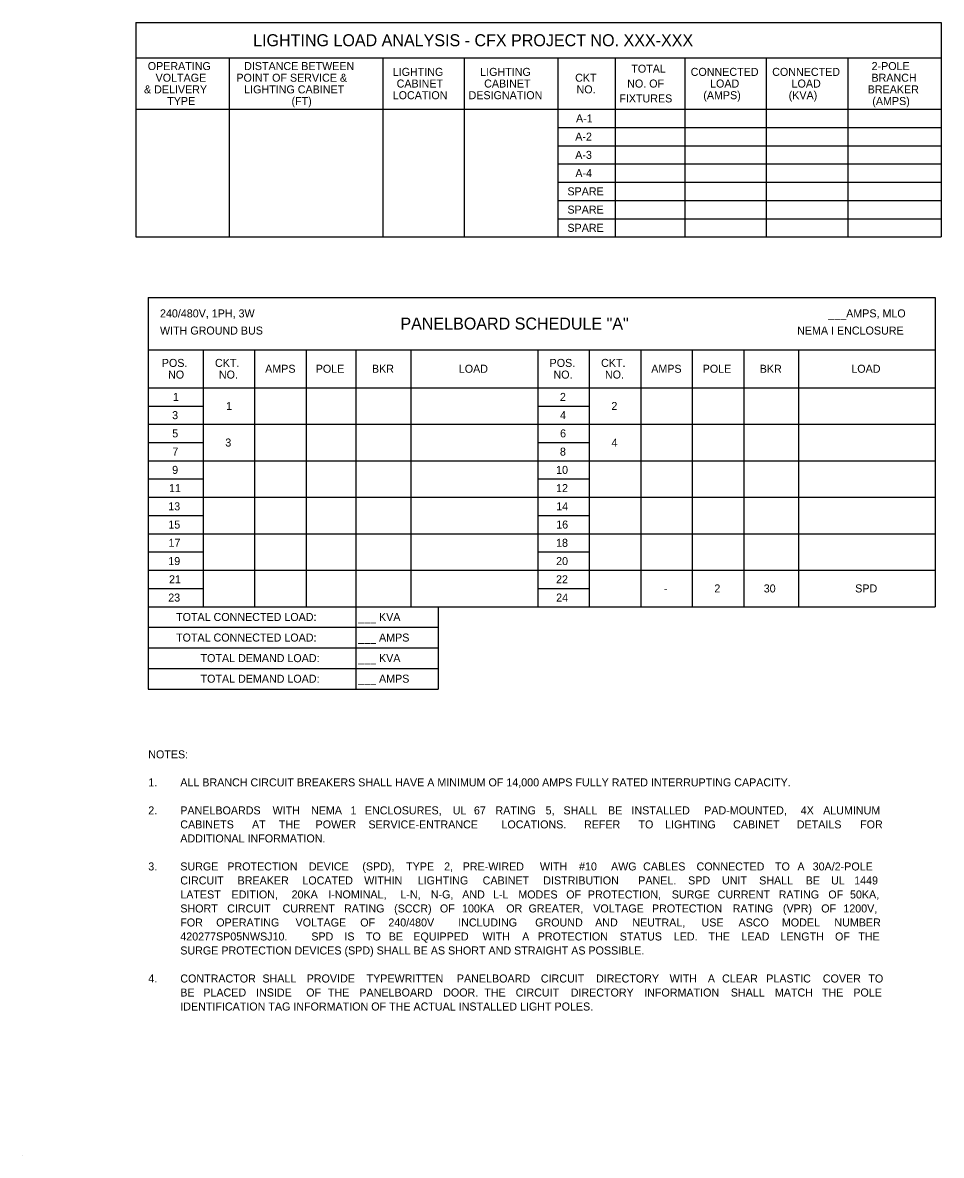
# Model space of a CAD drawing. Extents: x 856079 to 2148480, y 462635 to 2147771.
# Drawn here: x 2148464.67 to 2148472.7, y 2147761.57 to 2147771.47 of the extents above; entities that cross this region are included whole.
import ezdxf

# ---------------------------------------------------------------- set-up
doc = ezdxf.new("R2010")
doc.units = 0
for name, color, linetype in [('AdhocPoint_dp', 7, 'Continuous'), ('FLMap5', 7, 'Continuous'), ('SumBoxBorder_dp', 7, 'Continuous'), ('SumBoxLines_dp', 7, 'Continuous'), ('TextNotes', 7, 'Continuous')]:
    doc.layers.add(name, color=color, linetype=linetype)

msp = doc.modelspace()

# ---------------------------------------------------------------- linework, layer by layer
at = {"layer": 'AdhocPoint_dp'}
msp.add_line((2148464.6682, 2147761.5674), (2148464.6682, 2147761.5674), dxfattribs=at)
at = {"layer": 'SumBoxBorder_dp'}
for p, q in [((2148465.6565, 2147771.4724), (2148472.699, 2147771.4724)), ((2148465.6565, 2147771.4724), (2148465.6565, 2147769.5984)), ((2148472.699, 2147771.4724), (2148472.699, 2147769.5984)), ((2148465.6565, 2147771.1649), (2148472.699, 2147771.1649)), ((2148465.6565, 2147771.1649), (2148472.699, 2147771.1649)), ((2148465.6565, 2147769.5984), (2148472.699, 2147769.5984)), ((2148465.7662, 2147769.0699), (2148472.6437, 2147769.0699)), ((2148465.7662, 2147769.0699), (2148465.7662, 2147765.6454)), ((2148472.6437, 2147769.0699), (2148472.6437, 2147766.3654)), ((2148465.7662, 2147768.6124), (2148472.6437, 2147768.6124)), ((2148465.7662, 2147768.6124), (2148472.6437, 2147768.6124)), ((2148465.7662, 2147766.3654), (2148472.6437, 2147766.3654)), ((2148465.7662, 2147766.3654), (2148472.6437, 2147766.3654)), ((2148467.5812, 2147766.3654), (2148467.5812, 2147765.6454)), ((2148468.3012, 2147766.3654), (2148468.3012, 2147765.6454)), ((2148468.3012, 2147766.3654), (2148468.3012, 2147765.6454)), ((2148465.7662, 2147766.1854), (2148468.3012, 2147766.1854)), ((2148465.7662, 2147766.1854), (2148468.3012, 2147766.1854)), ((2148465.7662, 2147766.0054), (2148468.3012, 2147766.0054)), ((2148465.7662, 2147766.0054), (2148468.3012, 2147766.0054)), ((2148465.7662, 2147765.8254), (2148468.3012, 2147765.8254)), ((2148465.7662, 2147765.8254), (2148468.3012, 2147765.8254)), ((2148465.7662, 2147765.6454), (2148468.3012, 2147765.6454))]:
    msp.add_line(p, q, dxfattribs=at)
at = {"layer": 'SumBoxLines_dp'}
for p, q in [((2148466.474, 2147771.1649), (2148466.474, 2147769.5984)), ((2148466.474, 2147771.1649), (2148466.474, 2147769.5984)), ((2148467.8165, 2147771.1649), (2148467.8165, 2147769.5984)), ((2148467.8165, 2147771.1649), (2148467.8165, 2147769.5984)), ((2148468.529, 2147771.1649), (2148468.529, 2147769.5984)), ((2148468.529, 2147771.1649), (2148468.529, 2147769.5984)), ((2148469.3465, 2147771.1649), (2148469.3465, 2147769.5984)), ((2148469.3465, 2147771.1649), (2148469.3465, 2147769.5984)), ((2148469.849, 2147771.1649), (2148469.849, 2147769.5984)), ((2148469.849, 2147771.1649), (2148469.849, 2147769.5984)), ((2148470.4565, 2147771.1649), (2148470.4565, 2147769.5984)), ((2148470.4565, 2147771.1649), (2148470.4565, 2147769.5984)), ((2148471.169, 2147771.1649), (2148471.169, 2147769.5984)), ((2148471.169, 2147771.1649), (2148471.169, 2147769.5984)), ((2148471.8815, 2147771.1649), (2148471.8815, 2147769.5984)), ((2148471.8815, 2147771.1649), (2148471.8815, 2147769.5984)), ((2148465.6565, 2147770.7149), (2148472.699, 2147770.7149)), ((2148465.6565, 2147770.7149), (2148472.699, 2147770.7149)), ((2148469.3465, 2147770.5554), (2148472.699, 2147770.5554)), ((2148469.3465, 2147770.5554), (2148472.699, 2147770.5554)), ((2148469.3465, 2147770.3959), (2148472.699, 2147770.3959)), ((2148469.3465, 2147770.3959), (2148472.699, 2147770.3959)), ((2148469.3465, 2147770.2364), (2148472.699, 2147770.2364)), ((2148469.3465, 2147770.2364), (2148472.699, 2147770.2364)), ((2148469.3465, 2147770.0769), (2148472.699, 2147770.0769)), ((2148469.3465, 2147770.0769), (2148472.699, 2147770.0769)), ((2148469.3465, 2147769.9174), (2148472.699, 2147769.9174)), ((2148469.3465, 2147769.9174), (2148472.699, 2147769.9174)), ((2148469.3465, 2147769.7579), (2148472.699, 2147769.7579)), ((2148469.3465, 2147769.7579), (2148472.699, 2147769.7579)), ((2148466.2462, 2147768.6124), (2148466.2462, 2147766.3654)), ((2148466.2462, 2147768.6124), (2148466.2462, 2147766.3654)), ((2148466.6962, 2147768.6124), (2148466.6962, 2147766.3654)), ((2148466.6962, 2147768.6124), (2148466.6962, 2147766.3654)), ((2148467.1462, 2147768.6124), (2148467.1462, 2147766.3654)), ((2148467.1462, 2147768.6124), (2148467.1462, 2147766.3654)), ((2148467.5812, 2147768.6124), (2148467.5812, 2147766.3654)), ((2148467.5812, 2147768.6124), (2148467.5812, 2147766.3654)), ((2148468.0612, 2147768.6124), (2148468.0612, 2147766.3654)), ((2148468.0612, 2147768.6124), (2148468.0612, 2147766.3654)), ((2148469.1712, 2147768.6124), (2148469.1712, 2147766.3654)), ((2148469.1712, 2147768.6124), (2148469.1712, 2147766.3654)), ((2148469.6212, 2147768.6124), (2148469.6212, 2147766.3654)), ((2148469.6212, 2147768.6124), (2148469.6212, 2147766.3654)), ((2148470.0712, 2147768.6124), (2148470.0712, 2147766.3654)), ((2148470.0712, 2147768.6124), (2148470.0712, 2147766.3654)), ((2148470.5212, 2147768.6124), (2148470.5212, 2147766.3654)), ((2148470.5212, 2147768.6124), (2148470.5212, 2147766.3654)), ((2148470.9712, 2147768.6124), (2148470.9712, 2147766.3654)), ((2148470.9712, 2147768.6124), (2148470.9712, 2147766.3654)), ((2148471.4512, 2147768.6124), (2148471.4512, 2147766.3654)), ((2148471.4512, 2147768.6124), (2148471.4512, 2147766.3654)), ((2148465.7662, 2147768.2794), (2148472.6437, 2147768.2794)), ((2148465.7662, 2147768.2794), (2148472.6437, 2147768.2794)), ((2148465.7662, 2147768.1199), (2148466.2462, 2147768.1199)), ((2148465.7662, 2147768.1199), (2148466.2462, 2147768.1199)), ((2148469.1712, 2147768.1199), (2148469.6212, 2147768.1199)), ((2148465.7662, 2147767.9604), (2148472.6437, 2147767.9604)), ((2148465.7662, 2147767.9604), (2148472.6437, 2147767.9604)), ((2148465.7662, 2147767.8009), (2148466.2462, 2147767.8009)), ((2148465.7662, 2147767.8009), (2148466.2462, 2147767.8009)), ((2148469.1712, 2147767.8009), (2148469.6212, 2147767.8009)), ((2148469.1712, 2147767.8009), (2148469.6212, 2147767.8009)), ((2148465.7662, 2147767.6414), (2148469.1712, 2147767.6414)), ((2148465.7662, 2147767.6414), (2148472.6437, 2147767.6414)), ((2148469.6212, 2147767.6414), (2148472.6437, 2147767.6414)), ((2148465.7662, 2147767.4819), (2148466.2462, 2147767.4819)), ((2148465.7662, 2147767.4819), (2148466.2462, 2147767.4819)), ((2148469.1712, 2147767.4819), (2148469.6212, 2147767.4819)), ((2148469.1712, 2147767.4819), (2148469.6212, 2147767.4819)), ((2148465.7662, 2147767.3224), (2148472.6437, 2147767.3224)), ((2148465.7662, 2147767.3224), (2148472.6437, 2147767.3224)), ((2148465.7662, 2147767.1629), (2148466.2462, 2147767.1629)), ((2148465.7662, 2147767.1629), (2148466.2462, 2147767.1629)), ((2148469.1712, 2147767.1629), (2148469.6212, 2147767.1629)), ((2148465.7662, 2147767.0034), (2148472.6437, 2147767.0034)), ((2148465.7662, 2147767.0034), (2148472.6437, 2147767.0034)), ((2148465.7662, 2147766.8439), (2148466.2462, 2147766.8439)), ((2148465.7662, 2147766.8439), (2148466.2462, 2147766.8439)), ((2148469.1712, 2147766.8439), (2148469.6212, 2147766.8439)), ((2148469.1712, 2147766.8439), (2148469.6212, 2147766.8439)), ((2148465.7662, 2147766.6844), (2148469.1712, 2147766.6844)), ((2148465.7662, 2147766.6844), (2148472.6437, 2147766.6844)), ((2148469.6212, 2147766.6844), (2148472.6437, 2147766.6844)), ((2148465.7662, 2147766.5249), (2148466.2462, 2147766.5249)), ((2148465.7662, 2147766.5249), (2148466.2462, 2147766.5249)), ((2148469.1712, 2147766.5249), (2148469.6212, 2147766.5249)), ((2148469.1712, 2147766.5249), (2148469.6212, 2147766.5249))]:
    msp.add_line(p, q, dxfattribs=at)

# ---------------------------------------------------------------- texts
at = {"layer": 'FLMap5'}
for s, height, p in [('LIGHTING LOAD ANALYSIS - CFX PROJECT NO. XXX-XXX', 0.105, (2148466.6829, 2147771.2662)), ('OPERATING', 0.07, (2148465.7617, 2147771.0579)), ('DISTANCE BETWEEN', 0.07, (2148466.6045, 2147771.0579)), ('TOTAL', 0.07, (2148469.9891, 2147771.0349)), ('2-POLE', 0.07, (2148472.0893, 2147771.0579)), ('VOLTAGE', 0.07, (2148465.8304, 2147770.9559)), ('POINT OF SERVICE &', 0.07, (2148466.5368, 2147770.9559)), ('LIGHTING', 0.07, (2148467.9031, 2147771.0069)), ('LIGHTING', 0.07, (2148468.6681, 2147771.0069)), ('CKT', 0.07, (2148469.4979, 2147770.9559)), ('CONNECTED', 0.07, (2148470.5081, 2147771.0069)), ('CONNECTED', 0.07, (2148471.2206, 2147771.0069)), ('BRANCH', 0.07, (2148472.0883, 2147770.9559)), ('& DELIVERY', 0.07, (2148465.7289, 2147770.8539)), ('LIGHTING CABINET', 0.07, (2148466.605, 2147770.8539)), ('CABINET', 0.07, (2148467.9374, 2147770.9049)), ('CABINET', 0.07, (2148468.7024, 2147770.9049)), ('NO.', 0.07, (2148469.5101, 2147770.8539)), ('NO. OF', 0.07, (2148469.9528, 2147770.9049)), ('LOAD', 0.07, (2148470.6775, 2147770.9049)), ('LOAD', 0.07, (2148471.39, 2147770.9049)), ('BREAKER', 0.07, (2148472.0553, 2147770.8539)), ('TYPE', 0.07, (2148465.932, 2147770.7519)), ('(FT)', 0.07, (2148467.0184, 2147770.7519)), ('LOCATION', 0.07, (2148467.9031, 2147770.8029)), ('DESIGNATION', 0.07, (2148468.5664, 2147770.8029)), ('FIXTURES', 0.07, (2148469.8842, 2147770.7749)), ('(AMPS)', 0.07, (2148470.6182, 2147770.8029)), ('(KVA)', 0.07, (2148471.3646, 2147770.8029)), ('(AMPS)', 0.07, (2148472.0957, 2147770.7519)), ('A-1', 0.07, (2148469.5054, 2147770.6002)), ('A-2', 0.07, (2148469.4986, 2147770.4407)), ('A-3', 0.07, (2148469.4986, 2147770.2812)), ('A-4', 0.07, (2148469.5, 2147770.1217)), ('SPARE', 0.07, (2148469.4306, 2147769.9622)), ('SPARE', 0.07, (2148469.4306, 2147769.8027)), ('SPARE', 0.07, (2148469.4306, 2147769.6432)), ('240/480V, 1PH, 3W', 0.07, (2148465.8687, 2147768.8949)), ('___AMPS, MLO', 0.07, (2148471.7109, 2147768.8949)), ('WITH GROUND BUS', 0.07, (2148465.8687, 2147768.7449)), ('PANELBOARD SCHEDULE "A"', 0.105, (2148467.9705, 2147768.7887)), ('NEMA I ENCLOSURE', 0.07, (2148471.4385, 2147768.7449)), ('POS.', 0.07, (2148465.8847, 2147768.4619)), ('CKT.', 0.07, (2148466.3497, 2147768.4619)), ('POS.', 0.07, (2148469.2747, 2147768.4619)), ('CKT.', 0.07, (2148469.7247, 2147768.4619)), ('NO', 0.07, (2148465.9394, 2147768.3599)), ('NO.', 0.07, (2148466.3835, 2147768.3599)), ('AMPS', 0.07, (2148466.7881, 2147768.4109)), ('POLE', 0.07, (2148467.2304, 2147768.4109)), ('BKR', 0.07, (2148467.7217, 2147768.4109)), ('LOAD', 0.07, (2148468.481, 2147768.4109)), ('NO.', 0.07, (2148469.3085, 2147768.3599)), ('NO.', 0.07, (2148469.7585, 2147768.3599)), ('AMPS', 0.07, (2148470.1631, 2147768.4109)), ('POLE', 0.07, (2148470.6129, 2147768.4109)), ('BKR', 0.07, (2148471.1117, 2147768.4109)), ('LOAD', 0.07, (2148471.9122, 2147768.4109)), ('1', 0.07, (2148465.9815, 2147768.1647)), ('2', 0.07, (2148469.3648, 2147768.1647)), ('1', 0.07, (2148466.4465, 2147768.0849)), ('2', 0.07, (2148469.8148, 2147768.0849)), ('3', 0.07, (2148465.9748, 2147768.0052)), ('4', 0.07, (2148469.3662, 2147768.0052)), ('5', 0.07, (2148465.9757, 2147767.8457)), ('6', 0.07, (2148469.3662, 2147767.8457)), ('3', 0.07, (2148466.4398, 2147767.7659)), ('4', 0.07, (2148469.8162, 2147767.7659)), ('7', 0.07, (2148465.9768, 2147767.6862)), ('8', 0.07, (2148469.365, 2147767.6862)), ('9', 0.07, (2148465.9752, 2147767.5267)), ('10', 0.07, (2148469.3315, 2147767.5267)), ('11', 0.07, (2148465.9477, 2147767.3672)), ('12', 0.07, (2148469.3309, 2147767.3672)), ('13', 0.07, (2148465.9409, 2147767.2077)), ('14', 0.07, (2148469.3323, 2147767.2077)), ('16', 0.07, (2148469.3323, 2147767.0482)), ('15', 0.07, (2148465.9418, 2147767.0482)), ('17', 0.07, (2148465.9429, 2147766.8887)), ('18', 0.07, (2148469.3312, 2147766.8887)), ('19', 0.07, (2148465.9413, 2147766.7292)), ('20', 0.07, (2148469.3315, 2147766.7292)), ('21', 0.07, (2148465.9477, 2147766.5697)), ('22', 0.07, (2148469.3309, 2147766.5697)), ('2', 0.07, (2148470.7148, 2147766.4899)), ('30', 0.07, (2148471.1465, 2147766.4899)), ('SPD', 0.07, (2148471.9461, 2147766.4899)), ('23', 0.07, (2148465.9409, 2147766.4102)), ('24', 0.07, (2148469.3323, 2147766.4102)), ('-', 0.07, (2148470.2727, 2147766.4899)), ('TOTAL CONNECTED LOAD:', 0.07, (2148466.0093, 2147766.2404)), ('___ KVA', 0.07, (2148467.6012, 2147766.2404)), ('TOTAL CONNECTED LOAD:', 0.07, (2148466.0093, 2147766.0604)), ('___ AMPS', 0.07, (2148467.6012, 2147766.0604)), ('TOTAL DEMAND LOAD:', 0.07, (2148466.2233, 2147765.8804)), ('___ KVA', 0.07, (2148467.6012, 2147765.8804)), ('TOTAL DEMAND LOAD:', 0.07, (2148466.2233, 2147765.7004)), ('___ AMPS', 0.07, (2148467.6012, 2147765.7004))]:
    msp.add_text(s, height=height, dxfattribs=at).set_placement(p)
at = {"layer": 'TextNotes'}
for s, p in [('NOTES:', (2148465.7662, 2147765.0389)), ('1.', (2148465.7662, 2147764.7939)), ('ALL BRANCH CIRCUIT BREAKERS SHALL HAVE A MINIMUM OF 14,000 AMPS FULLY RATED INTERRUPTING CAPACITY.', (2148466.0462, 2147764.7939)), ('2.', (2148465.7662, 2147764.5489)), ('PANELBOARDS ', (2148466.0462, 2147764.5489)), ('WITH ', (2148466.8531, 2147764.5489)), ('NEMA ', (2148467.1892, 2147764.5489)), ('1 ', (2148467.5342, 2147764.5489)), ('ENCLOSURES, ', (2148467.6599, 2147764.5489)), ('UL ', (2148468.4276, 2147764.5489)), ('67 ', (2148468.613, 2147764.5489)), ('RATING ', (2148468.8015, 2147764.5489)), ('5, ', (2148469.2397, 2147764.5489)), ('SHALL ', (2148469.396, 2147764.5489)), ('BE ', (2148469.7854, 2147764.5489)), ('INSTALLED ', (2148469.9904, 2147764.5489)), ('PAD-MOUNTED, ', (2148470.6258, 2147764.5489)), ('4X ', (2148471.4699, 2147764.5489)), ('ALUMINUM ', (2148471.6658, 2147764.5489)), ('CABINETS ', (2148466.0462, 2147764.4264)), ('AT ', (2148466.6733, 2147764.4264)), ('THE ', (2148466.9072, 2147764.4264)), ('POWER ', (2148467.229, 2147764.4264)), ('SERVICE-ENTRANCE ', (2148467.691, 2147764.4264)), ('LOCATIONS. ', (2148468.8538, 2147764.4264)), (' REFER ', (2148469.5492, 2147764.4264)), ('TO ', (2148470.0517, 2147764.4264)), ('LIGHTING ', (2148470.2851, 2147764.4264)), ('CABINET ', (2148470.8792, 2147764.4264)), ('DETAILS ', (2148471.4355, 2147764.4264)), ('FOR ', (2148471.9891, 2147764.4264)), ('ADDITIONAL INFORMATION.', (2148466.0462, 2147764.3039)), ('3.', (2148465.7662, 2147764.0589)), ('SURGE ', (2148466.0462, 2147764.0589)), ('PROTECTION ', (2148466.4572, 2147764.0589)), ('DEVICE ', (2148467.17, 2147764.0589)), ('(SPD), ', (2148467.6377, 2147764.0589)), ('TYPE ', (2148468.0205, 2147764.0589)), ('2, ', (2148468.3525, 2147764.0589)), ('PRE-WIRED ', (2148468.5148, 2147764.0589)), ('WITH ', (2148469.1899, 2147764.0589)), ('#10 ', (2148469.5321, 2147764.0589)), ('AWG ', (2148469.8114, 2147764.0589)), ('CABLES ', (2148470.0921, 2147764.0589)), ('CONNECTED ', (2148470.5591, 2147764.0589)), ('TO ', (2148471.245, 2147764.0589)), ('A ', (2148471.4413, 2147764.0589)), ('30A/2-POLE ', (2148471.5744, 2147764.0589)), ('CIRCUIT ', (2148466.0462, 2147763.9364)), ('BREAKER ', (2148466.5472, 2147763.9364)), ('LOCATED ', (2148467.1135, 2147763.9364)), ('WITHIN ', (2148467.654, 2147763.9364)), ('LIGHTING ', (2148468.1216, 2147763.9364)), ('CABINET ', (2148468.6893, 2147763.9364)), ('DISTRIBUTION ', (2148469.2193, 2147763.9364)), ('PANEL. ', (2148470.0496, 2147763.9364)), ('SPD ', (2148470.4858, 2147763.9364)), ('UNIT ', (2148470.7817, 2147763.9364)), ('SHALL ', (2148471.1069, 2147763.9364)), ('BE ', (2148471.5131, 2147763.9364)), ('UL ', (2148471.7348, 2147763.9364)), ('1449 ', (2148471.937, 2147763.9364)), ('LATEST ', (2148466.0462, 2147763.8139)), ('EDITION, ', (2148466.4942, 2147763.8139)), ('20KA ', (2148467.0192, 2147763.8139)), ('I-NOMINAL, ', (2148467.3393, 2147763.8139)), ('L-N, ', (2148467.9703, 2147763.8139)), ('N-G, ', (2148468.2361, 2147763.8139)), ('AND ', (2148468.5106, 2147763.8139)), ('L-L ', (2148468.7797, 2147763.8139)), ('MODES ', (2148469.0011, 2147763.8139)), ('OF ', (2148469.4198, 2147763.8139)), ('PROTECTION, ', (2148469.6094, 2147763.8139)), ('SURGE ', (2148470.3427, 2147763.8139)), ('CURRENT ', (2148470.7435, 2147763.8139)), ('RATING ', (2148471.2769, 2147763.8139)), ('OF ', (2148471.7111, 2147763.8139)), ('50KA, ', (2148471.9007, 2147763.8139)), ('SHORT ', (2148466.0462, 2147763.6914)), ('CIRCUIT ', (2148466.4564, 2147763.6914)), ('CURRENT ', (2148466.9403, 2147763.6914)), ('RATING ', (2148467.4775, 2147763.6914)), ('(SCCR) ', (2148467.9154, 2147763.6914)), ('OF ', (2148468.3157, 2147763.6914)), ('100KA ', (2148468.5091, 2147763.6914)), ('OR ', (2148468.8958, 2147763.6914)), ('GREATER, ', (2148469.0907, 2147763.6914)), ('VOLTAGE ', (2148469.656, 2147763.6914)), ('PROTECTION ', (2148470.1694, 2147763.6914)), ('RATING ', (2148470.8758, 2147763.6914)), ('(VPR) ', (2148471.3137, 2147763.6914)), ('OF ', (2148471.649, 2147763.6914)), ('1200V, ', (2148471.8424, 2147763.6914)), ('FOR ', (2148466.0462, 2147763.5689)), ('OPERATING ', (2148466.3603, 2147763.5689)), ('VOLTAGE ', (2148467.0539, 2147763.5689)), ('OF ', (2148467.6192, 2147763.5689)), ('240/480V ', (2148467.8646, 2147763.5689)), ('INCLUDING ', (2148468.4754, 2147763.5689)), ('GROUND ', (2148469.1484, 2147763.5689)), ('AND ', (2148469.6727, 2147763.5689)), ('NEUTRAL, ', (2148469.9976, 2147763.5689)), ('USE ', (2148470.6026, 2147763.5689)), ('ASCO ', (2148470.9263, 2147763.5689)), ('MODEL ', (2148471.305, 2147763.5689)), ('NUMBER ', (2148471.7642, 2147763.5689)), ('420277SP05NWSJ10. ', (2148466.0462, 2147763.4464)), ('SPD ', (2148467.1915, 2147763.4464)), ('IS ', (2148467.4803, 2147763.4464)), ('TO ', (2148467.6688, 2147763.4464)), ('BE ', (2148467.8687, 2147763.4464)), ('EQUIPPED ', (2148468.0833, 2147763.4464)), ('WITH ', (2148468.6887, 2147763.4464)), ('A ', (2148469.0345, 2147763.4464)), ('PROTECTION ', (2148469.1711, 2147763.4464)), ('STATUS ', (2148469.8875, 2147763.4464)), ('LED. ', (2148470.3602, 2147763.4464)), ('THE ', (2148470.6639, 2147763.4464)), ('LEAD ', (2148470.9522, 2147763.4464)), ('LENGTH ', (2148471.2925, 2147763.4464)), ('OF ', (2148471.7697, 2147763.4464)), ('THE ', (2148471.973, 2147763.4464)), ('SURGE PROTECTION DEVICES (SPD) SHALL BE AS SHORT AND STRAIGHT AS POSSIBLE.', (2148466.0462, 2147763.3239)), ('4.', (2148465.7662, 2147763.0789)), ('CONTRACTOR ', (2148466.0462, 2147763.0789)), ('SHALL ', (2148466.764, 2147763.0789)), ('PROVIDE ', (2148467.1512, 2147763.0789)), ('TYPEWRITTEN ', (2148467.6747, 2147763.0789)), ('PANELBOARD ', (2148468.4642, 2147763.0789)), ('CIRCUIT ', (2148469.1981, 2147763.0789)), ('DIRECTORY ', (2148469.6801, 2147763.0789)), ('WITH ', (2148470.3241, 2147763.0789)), ('A ', (2148470.658, 2147763.0789)), ('CLEAR ', (2148470.7827, 2147763.0789)), ('PLASTIC ', (2148471.1687, 2147763.0789)), ('COVER ', (2148471.663, 2147763.0789)), ('TO ', (2148472.0613, 2147763.0789)), ('BE ', (2148466.0462, 2147762.9564)), ('PLACED ', (2148466.2474, 2147762.9564)), ('INSIDE ', (2148466.7086, 2147762.9564)), ('OF ', (2148467.1467, 2147762.9564)), ('THE ', (2148467.3367, 2147762.9564)), ('PANELBOARD ', (2148467.6116, 2147762.9564)), ('DOOR. ', (2148468.344, 2147762.9564)), ('THE ', (2148468.7037, 2147762.9564)), ('CIRCUIT ', (2148468.9785, 2147762.9564)), ('DIRECTORY ', (2148469.4591, 2147762.9564)), ('INFORMATION ', (2148470.1016, 2147762.9564)), ('SHALL ', (2148470.8585, 2147762.9564)), ('MATCH ', (2148471.2442, 2147762.9564)), ('THE ', (2148471.6548, 2147762.9564)), ('POLE ', (2148471.9297, 2147762.9564)), ('IDENTIFICATION TAG INFORMATION OF THE ACTUAL INSTALLED LIGHT POLES.', (2148466.0462, 2147762.8339))]:
    msp.add_text(s, height=0.07, dxfattribs=at).set_placement(p)

doc.saveas('drawing.dxf')
